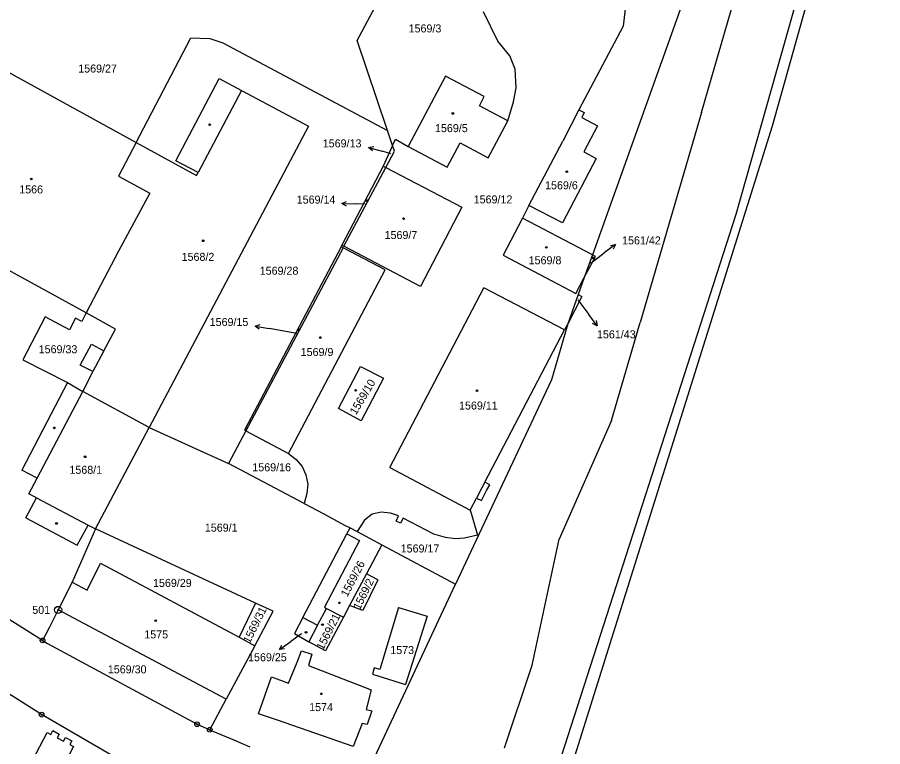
# Model space of a CAD drawing. Extents: x -763296 to -761805, y -1153670 to -1152034.
# Drawn here: x -762375.6 to -762191.7, y -1152457.5 to -1152302.6 of the extents above; entities that cross this region are included whole.
import ezdxf

# ---------------------------------------------------------------- set-up
doc = ezdxf.new("R2010")
doc.units = 0
for name, color, linetype in [('Vrstva 1', 7, 'Continuous'), ('Vrstva 13', 7, 'Continuous'), ('Vrstva 16', 7, 'Continuous'), ('Vrstva 17', 7, 'Continuous'), ('Vrstva 18', 7, 'Continuous'), ('Vrstva 19', 7, 'Continuous'), ('Vrstva 24', 7, 'Continuous'), ('Vrstva 25', 7, 'Continuous'), ('Vrstva 4', 7, 'Continuous')]:
    doc.layers.add(name, color=color, linetype=linetype)

msp = doc.modelspace()

# ---------------------------------------------------------------- linework, layer by layer
at = {"layer": 'Vrstva 1'}
for p, q in [((-762230.19, -1152322.79), (-762191.71, -1152189.12)), ((-762222.86, -1152344.39), (-762200.55, -1152265.44)), ((-762303.34, -1152307.53), (-762285.97, -1152274.85)), ((-762227.29, -1152280), (-762253.37, -1152353.02)), ((-762245.76, -1152295.43), (-762246.88, -1152304.45)), ((-762273.5, -1152307.66), (-762276.53, -1152301.44)), ((-762246.88, -1152304.45), (-762256.28, -1152322.2)), ((-762350.33, -1152329.15), (-762338.73, -1152306.91)), ((-762338.73, -1152306.91), (-762334.65, -1152307.08)), ((-762334.65, -1152307.08), (-762331.9, -1152307.96)), ((-762296.9, -1152326.63), (-762303.34, -1152307.53)), ((-762270.93, -1152310.77), (-762273.5, -1152307.66)), ((-762331.9, -1152307.96), (-762296.9, -1152326.63)), ((-762269.79, -1152313.56), (-762270.93, -1152310.77)), ((-762380.75, -1152312.44), (-762350.33, -1152329.15)), ((-762284.62, -1152315.07), (-762292.52, -1152330.03)), ((-762276.35, -1152319.42), (-762284.62, -1152315.07)), ((-762269.57, -1152317.55), (-762269.79, -1152313.56)), ((-762341.9, -1152333.04), (-762332.67, -1152315.59)), ((-762332.67, -1152315.59), (-762327.95, -1152318.09)), ((-762327.95, -1152318.09), (-762313.68, -1152325.69)), ((-762270.12, -1152320.5), (-762269.57, -1152317.55)), ((-762277.36, -1152321.36), (-762276.35, -1152319.42)), ((-762271.34, -1152324.54), (-762270.12, -1152320.5)), ((-762271.34, -1152324.54), (-762277.36, -1152321.36)), ((-762256.28, -1152322.2), (-762259.69, -1152328.87)), ((-762256.28, -1152322.2), (-762255.15, -1152322.77)), ((-762255.15, -1152322.77), (-762255.65, -1152323.83)), ((-762255.65, -1152323.83), (-762252.28, -1152325.64)), ((-762230.19, -1152322.79), (-762243.22, -1152367.38)), ((-762313.68, -1152325.69), (-762347.57, -1152389.71)), ((-762275.54, -1152332.41), (-762271.34, -1152324.54)), ((-762252.28, -1152325.64), (-762255.18, -1152331.17)), ((-762295.83, -1152329.8), (-762296.9, -1152326.63)), ((-762350.33, -1152329.15), (-762354.05, -1152336.29)), ((-762350.33, -1152329.15), (-762337.5, -1152336.19)), ((-762295.83, -1152329.8), (-762297.85, -1152334.16)), ((-762295.83, -1152329.8), (-762295.21, -1152328.47)), ((-762295.43, -1152330.99), (-762295.83, -1152329.8)), ((-762295.21, -1152328.47), (-762292.52, -1152330.03)), ((-762284.24, -1152334.41), (-762281.5, -1152329.22)), ((-762281.5, -1152329.22), (-762275.54, -1152332.41)), ((-762266.91, -1152342.54), (-762259.69, -1152328.87)), ((-762297.28, -1152334.47), (-762295.43, -1152330.99)), ((-762292.52, -1152330.03), (-762284.24, -1152334.41)), ((-762255.18, -1152331.17), (-762252.57, -1152332.54)), ((-762337.16, -1152335.54), (-762341.9, -1152333.04)), ((-762252.57, -1152332.54), (-762259.76, -1152346.25)), ((-762297.85, -1152334.16), (-762306.64, -1152350.96)), ((-762306.17, -1152351.2), (-762297.28, -1152334.47)), ((-762297.85, -1152334.16), (-762297.28, -1152334.47)), ((-762297.28, -1152334.47), (-762281.12, -1152342.92)), ((-762354.05, -1152336.29), (-762347.44, -1152339.96)), ((-762337.5, -1152336.19), (-762337.16, -1152335.54)), ((-762347.44, -1152339.96), (-762354.06, -1152352.23)), ((-762266.91, -1152342.54), (-762268.23, -1152345.21)), ((-762259.76, -1152346.25), (-762266.91, -1152342.54)), ((-762281.12, -1152342.92), (-762289.94, -1152359.73)), ((-762259.95, -1152459.53), (-762222.86, -1152344.39)), ((-762360.92, -1152365.36), (-762398.44, -1152344.76)), ((-762268.23, -1152345.21), (-762272.34, -1152353.13)), ((-762253.37, -1152353.02), (-762268.23, -1152345.21)), ((-762306.75, -1152351.29), (-762327.3, -1152390.26)), ((-762306.34, -1152351.51), (-762327.02, -1152390.41)), ((-762306.64, -1152350.96), (-762306.75, -1152351.29)), ((-762306.34, -1152351.51), (-762306.75, -1152351.29)), ((-762306.64, -1152350.96), (-762306.17, -1152351.2)), ((-762297.42, -1152356.21), (-762306.34, -1152351.51)), ((-762289.94, -1152359.73), (-762306.17, -1152351.2)), ((-762354.06, -1152352.23), (-762360.92, -1152365.36)), ((-762272.34, -1152353.13), (-762256.88, -1152361.23)), ((-762253.37, -1152353.02), (-762255.11, -1152357.86)), ((-762255.11, -1152357.86), (-762252.74, -1152353.36)), ((-762252.74, -1152353.36), (-762253.37, -1152353.02)), ((-762317.97, -1152395.21), (-762297.42, -1152356.21)), ((-762256.88, -1152361.23), (-762255.11, -1152357.86)), ((-762255.11, -1152357.86), (-762256.41, -1152361.48)), ((-762296.43, -1152398.22), (-762276.43, -1152360.01)), ((-762259.32, -1152368.96), (-762276.43, -1152360.01)), ((-762256.41, -1152361.48), (-762258.64, -1152367.67)), ((-762255.62, -1152361.89), (-762258.64, -1152367.67)), ((-762256.41, -1152361.48), (-762255.62, -1152361.89)), ((-762369.67, -1152366.21), (-762374.41, -1152375.3)), ((-762364.5, -1152368.95), (-762369.67, -1152366.21)), ((-762363.21, -1152366.51), (-762364.5, -1152368.95)), ((-762361.89, -1152367.21), (-762363.21, -1152366.51)), ((-762360.92, -1152365.36), (-762361.89, -1152367.21)), ((-762354.69, -1152368.78), (-762360.92, -1152365.36)), ((-762258.64, -1152367.67), (-762262.06, -1152379.6)), ((-762258.64, -1152367.67), (-762259.32, -1152368.96)), ((-762249.33, -1152388.23), (-762243.22, -1152367.38)), ((-762357.16, -1152373.45), (-762354.69, -1152368.78)), ((-762276.23, -1152401.31), (-762259.32, -1152368.96)), ((-762362.22, -1152376.45), (-762359.85, -1152372.03)), ((-762359.85, -1152372.03), (-762357.16, -1152373.45)), ((-762374.41, -1152375.3), (-762364.88, -1152380.16)), ((-762359.5, -1152377.84), (-762362.22, -1152376.45)), ((-762307.32, -1152385.68), (-762302.65, -1152376.73)), ((-762302.65, -1152376.73), (-762297.76, -1152379.23)), ((-762361.55, -1152381.86), (-762359.5, -1152377.84)), ((-762297.76, -1152379.23), (-762302.49, -1152388.27)), ((-762364.88, -1152380.16), (-762374.65, -1152398.73)), ((-762364.88, -1152380.16), (-762361.64, -1152382.03)), ((-762262.06, -1152379.6), (-762282.46, -1152422.96)), ((-762361.64, -1152382.03), (-762361.55, -1152381.86)), ((-762347.57, -1152389.71), (-762361.64, -1152382.03)), ((-762302.49, -1152388.27), (-762307.32, -1152385.68)), ((-762249.33, -1152388.23), (-762260.43, -1152413.42)), ((-762358.97, -1152411.25), (-762347.57, -1152389.71)), ((-762347.57, -1152389.71), (-762330.69, -1152397.32)), ((-762327.02, -1152390.41), (-762330.69, -1152397.32)), ((-762327.3, -1152390.26), (-762327.02, -1152390.41)), ((-762327.02, -1152390.41), (-762317.97, -1152395.21)), ((-762317.97, -1152395.21), (-762316.34, -1152396.49)), ((-762314.61, -1152405.86), (-762330.69, -1152397.32)), ((-762316.34, -1152396.49), (-762315.07, -1152397.96)), ((-762371.36, -1152400.45), (-762374.65, -1152398.73)), ((-762315.07, -1152397.96), (-762314.25, -1152399.74)), ((-762314.25, -1152399.74), (-762313.86, -1152401.71)), ((-762296.43, -1152398.22), (-762279.34, -1152407.25)), ((-762373.12, -1152403.79), (-762371.36, -1152400.45)), ((-762275.21, -1152401.85), (-762276.23, -1152401.31)), ((-762313.86, -1152401.71), (-762314.08, -1152403.72)), ((-762276.98, -1152405.22), (-762275.86, -1152403.09)), ((-762275.86, -1152403.09), (-762275.21, -1152401.85)), ((-762373.79, -1152408.9), (-762371.52, -1152404.64)), ((-762371.52, -1152404.64), (-762373.12, -1152403.79)), ((-762314.08, -1152403.72), (-762314.61, -1152405.86)), ((-762279.34, -1152407.25), (-762278, -1152404.68)), ((-762278, -1152404.68), (-762276.98, -1152405.22)), ((-762314.61, -1152405.86), (-762310.46, -1152408.07)), ((-762373.79, -1152408.9), (-762362.84, -1152414.72)), ((-762310.46, -1152408.07), (-762306.05, -1152410.42)), ((-762300.18, -1152408.14), (-762301.78, -1152409.4)), ((-762298.25, -1152407.69), (-762300.18, -1152408.14)), ((-762296.31, -1152407.87), (-762298.25, -1152407.69)), ((-762294.57, -1152408.49), (-762296.31, -1152407.87)), ((-762295.08, -1152409.59), (-762294.57, -1152408.49)), ((-762293.61, -1152408.94), (-762294.18, -1152410.01)), ((-762287.08, -1152412.35), (-762293.61, -1152408.94)), ((-762279.34, -1152407.25), (-762279.13, -1152407.92)), ((-762279.13, -1152407.92), (-762277.78, -1152412.6)), ((-762362.84, -1152414.72), (-762360.54, -1152410.45)), ((-762360.54, -1152410.45), (-762358.97, -1152411.25)), ((-762306.05, -1152410.42), (-762304.88, -1152411.04)), ((-762301.78, -1152409.4), (-762303.39, -1152411.82)), ((-762294.18, -1152410.01), (-762295.08, -1152409.59)), ((-762358.97, -1152411.25), (-762363.9, -1152422.54)), ((-762325, -1152427), (-762358.97, -1152411.25)), ((-762314.94, -1152430.08), (-762305.54, -1152412.31)), ((-762305.54, -1152412.31), (-762304.88, -1152411.04)), ((-762305.54, -1152412.31), (-762302.86, -1152413.71)), ((-762304.88, -1152411.04), (-762303.39, -1152411.82)), ((-762303.39, -1152411.82), (-762298.1, -1152414.65)), ((-762284.6, -1152413.05), (-762287.08, -1152412.35)), ((-762277.78, -1152412.6), (-762280.54, -1152413.23)), ((-762302.86, -1152413.71), (-762310.33, -1152427.9)), ((-762282.58, -1152413.35), (-762284.6, -1152413.05)), ((-762280.54, -1152413.23), (-762282.58, -1152413.35)), ((-762266.21, -1152440.18), (-762260.43, -1152413.42)), ((-762298.1, -1152414.65), (-762301.38, -1152420.8)), ((-762298.1, -1152414.65), (-762282.46, -1152422.96)), ((-762360.71, -1152424.22), (-762357.88, -1152418.55)), ((-762357.88, -1152418.55), (-762328.45, -1152434.26)), ((-762301.38, -1152420.8), (-762304.97, -1152427.52)), ((-762298.96, -1152422.05), (-762301.38, -1152420.8)), ((-762363.9, -1152422.54), (-762366.9, -1152428.44)), ((-762363.9, -1152422.54), (-762360.71, -1152424.22)), ((-762302.43, -1152465.69), (-762282.46, -1152422.96)), ((-762298.96, -1152422.05), (-762302.19, -1152428.57)), ((-762370.2, -1152434.94), (-762387.9, -1152423.92)), ((-762325, -1152427), (-762328.45, -1152434.26)), ((-762321.22, -1152428.75), (-762325, -1152427)), ((-762366.9, -1152428.44), (-762368.84, -1152432.27)), ((-762331.22, -1152447.4), (-762366.9, -1152428.44)), ((-762325.14, -1152436.06), (-762321.22, -1152428.75)), ((-762310.33, -1152427.9), (-762309.88, -1152428.13)), ((-762309.88, -1152428.13), (-762306.29, -1152430)), ((-762304.97, -1152427.52), (-762306.29, -1152430)), ((-762302.19, -1152428.57), (-762304.97, -1152427.52)), ((-762294.62, -1152427.97), (-762298.57, -1152441.12)), ((-762294.62, -1152427.97), (-762288.51, -1152429.8)), ((-762314.94, -1152430.08), (-762316.71, -1152433.47)), ((-762314.94, -1152430.08), (-762311.78, -1152431.71)), ((-762306.29, -1152430), (-762310.07, -1152437.11)), ((-762288.51, -1152429.8), (-762293.11, -1152444.3)), ((-762368.84, -1152432.27), (-762370.2, -1152434.94)), ((-762311.78, -1152431.71), (-762313.65, -1152435.23)), ((-762328.45, -1152434.26), (-762325.14, -1152436.06)), ((-762316.71, -1152433.47), (-762313.65, -1152435.23)), ((-762370.42, -1152450.7), (-762393.06, -1152436.49)), ((-762370.2, -1152434.94), (-762369.18, -1152435.6)), ((-762369.18, -1152435.6), (-762337.38, -1152452.75)), ((-762325.14, -1152436.06), (-762331.22, -1152447.4)), ((-762310.07, -1152437.11), (-762313.65, -1152435.23)), ((-762316.13, -1152439.57), (-762315.23, -1152437.12)), ((-762315.23, -1152437.12), (-762313.03, -1152437.87)), ((-762313.03, -1152437.87), (-762313.73, -1152440.27)), ((-762317.95, -1152443.98), (-762316.13, -1152439.57)), ((-762272.05, -1152457.76), (-762266.21, -1152440.18)), ((-762313.73, -1152440.27), (-762300.4, -1152445.4)), ((-762299.74, -1152440.77), (-762300.14, -1152442.07)), ((-762298.57, -1152441.12), (-762299.74, -1152440.77)), ((-762324.31, -1152450.52), (-762321.59, -1152442.68)), ((-762321.59, -1152442.68), (-762317.95, -1152443.98)), ((-762300.14, -1152442.07), (-762298.96, -1152442.44)), ((-762298.96, -1152442.44), (-762293.11, -1152444.3)), ((-762300.4, -1152445.4), (-762301.45, -1152449.57)), ((-762334.7, -1152453.89), (-762331.22, -1152447.4)), ((-762341.83, -1152467.23), (-762370.42, -1152450.7)), ((-762320.32, -1152451.9), (-762324.31, -1152450.52)), ((-762301.45, -1152449.57), (-762300.25, -1152449.87)), ((-762300.25, -1152449.87), (-762301.27, -1152452.79)), ((-762337.38, -1152452.75), (-762334.7, -1152453.89)), ((-762304.23, -1152457.49), (-762320.32, -1152451.9)), ((-762302.28, -1152452.55), (-762304.23, -1152457.49)), ((-762301.27, -1152452.79), (-762302.28, -1152452.55)), ((-762373.67, -1152462.84), (-762369.24, -1152454.47)), ((-762369.24, -1152454.47), (-762368.45, -1152454.88)), ((-762368.45, -1152454.88), (-762368.02, -1152454.09)), ((-762368.02, -1152454.09), (-762366.69, -1152454.82)), ((-762366.69, -1152454.82), (-762367.11, -1152455.6)), ((-762334.7, -1152453.89), (-762334.01, -1152454.19)), ((-762334.01, -1152454.19), (-762329.43, -1152456.14)), ((-762367.11, -1152455.6), (-762365.74, -1152456.32)), ((-762365.74, -1152456.32), (-762365.33, -1152455.53)), ((-762365.33, -1152455.53), (-762363.99, -1152456.26)), ((-762363.99, -1152456.26), (-762364.4, -1152457.03)), ((-762329.43, -1152456.14), (-762326.14, -1152457.54)), ((-762363.62, -1152457.44), (-762368.12, -1152465.82)), ((-762364.4, -1152457.03), (-762363.62, -1152457.44))]:
    msp.add_line(p, q, dxfattribs=at)
at = {"layer": 'Vrstva 13'}
for p, q in [((-762215.11, -1152325.64), (-762192.1, -1152243.03)), ((-762262.04, -1152475.19), (-762215.11, -1152325.64))]:
    msp.add_line(p, q, dxfattribs=at)
at = {"layer": 'Vrstva 16'}
for p, q in [((-762300.943, -1152330.202), (-762298.06, -1152331.03)), ((-762296.2, -1152331.56), (-762298.06, -1152331.03)), ((-762306.649, -1152342.143), (-762303.65, -1152342.22)), ((-762301.67, -1152342.27), (-762303.65, -1152342.22)), ((-762248.469, -1152350.808), (-762250.86, -1152352.62)), ((-762253.73, -1152354.8), (-762250.86, -1152352.62)), ((-762256.5, -1152362.57), (-762254.18, -1152365.7)), ((-762252.392, -1152368.109), (-762254.18, -1152365.7)), ((-762325.053, -1152368.142), (-762322.1, -1152368.67)), ((-762316.17, -1152369.73), (-762322.1, -1152368.67)), ((-762315.19, -1152433.56), (-762317.44, -1152435.16)), ((-762319.888, -1152436.894), (-762317.44, -1152435.16))]:
    msp.add_line(p, q, dxfattribs=at)
for points in [[(-762300.12, -1152330.958), (-762300.943, -1152330.202), (-762299.844, -1152329.997)], [(-762305.662, -1152342.668), (-762306.649, -1152342.143), (-762305.636, -1152341.669)], [(-762249.568, -1152351.013), (-762248.469, -1152350.808), (-762248.964, -1152351.81)], [(-762324.157, -1152368.81), (-762325.053, -1152368.142), (-762323.981, -1152367.826)], [(-762252.587, -1152367.008), (-762252.392, -1152368.109), (-762253.39, -1152367.604)], [(-762318.783, -1152436.724), (-762319.888, -1152436.894), (-762319.361, -1152435.908)]]:
    msp.add_lwpolyline(points, dxfattribs=at)
at = {"layer": 'Vrstva 24'}
for centre, radius in [((-762366.9, -1152428.44), 0.75), ((-762366.9, -1152428.44), 0.1), ((-762370.2, -1152434.94), 0.5), ((-762370.2, -1152434.94), 0.1), ((-762370.42, -1152450.7), 0.5), ((-762370.42, -1152450.7), 0.1), ((-762337.38, -1152452.75), 0.5), ((-762337.38, -1152452.75), 0.1), ((-762334.7, -1152453.89), 0.5), ((-762334.7, -1152453.89), 0.1)]:
    msp.add_circle(centre, radius, dxfattribs=at)
at = {"layer": 'Vrstva 25'}
for points in [[(-762307.04, -1152426.79), (-762306.95, -1152426.94), (-762307.04, -1152427.09), (-762307.22, -1152427.09), (-762307.31, -1152426.94), (-762307.22, -1152426.79)], [(-762314.16, -1152433.07), (-762314.07, -1152433.22), (-762314.16, -1152433.37), (-762314.34, -1152433.37), (-762314.43, -1152433.22), (-762314.34, -1152433.07)], [(-762310.91, -1152446.12), (-762310.82, -1152446.27), (-762310.91, -1152446.42), (-762311.09, -1152446.42), (-762311.18, -1152446.27), (-762311.09, -1152446.12)]]:
    msp.add_lwpolyline(points, close=True, dxfattribs=at)
for centre in [(-762283.05, -1152323), (-762334.71, -1152325.39), (-762258.83, -1152335.35), (-762372.6, -1152336.91), (-762301.32, -1152341.49), (-762293.49, -1152345.34), (-762336.08, -1152350.04), (-762263.18, -1152351.44), (-762253.26, -1152353.67), (-762315.8, -1152368.9), (-762311.21, -1152370.59), (-762303.69, -1152381.8), (-762277.9, -1152381.91), (-762367.71, -1152389.79), (-762361.17, -1152395.92), (-762367.25, -1152410.09), (-762346.17, -1152430.75), (-762310.74, -1152431.59)]:
    msp.add_circle(centre, 0.175, dxfattribs=at)
at = {"layer": 'Vrstva 4'}
for p, q in [((-762327.95, -1152318.09), (-762337.16, -1152335.54)), ((-762357.16, -1152373.45), (-762359.5, -1152377.84)), ((-762371.36, -1152400.45), (-762361.64, -1152382.03)), ((-762276.23, -1152401.31), (-762276.88, -1152402.55)), ((-762276.88, -1152402.55), (-762278, -1152404.68)), ((-762371.52, -1152404.64), (-762360.54, -1152410.45)), ((-762311.78, -1152431.71), (-762309.88, -1152428.13))]:
    msp.add_line(p, q, dxfattribs=at)

# ---------------------------------------------------------------- texts
at = {"layer": 'Vrstva 16'}
for s, p in [('1569/13', (-762310.677, -1152330.2)), ('1569/14', (-762316.213, -1152342.14)), ('1561/42', (-762247.077, -1152350.81)), ('1569/15', (-762334.707, -1152368.14)), ('1561/43', (-762252.417, -1152370.76)), ('1569/25', (-762326.55, -1152439.35))]:
    msp.add_text(s, height=1.7, dxfattribs=at).set_placement(p)
at = {"layer": 'Vrstva 17'}
msp.add_text('501', height=1.7, dxfattribs=at).set_placement((-762372.399, -1152429.29))
at = {"layer": 'Vrstva 18'}
for s, height, p in [('1569/3', 1.7, (-762292.438, -1152305.78)), ('1569/27', 1.7, (-762362.634, -1152314.3)), ('1569/13', 0.1, (-762296.45, -1152331.56)), ('1569/12', 1.7, (-762278.616, -1152342.1)), ('1569/28', 1.7, (-762324.074, -1152357.25)), ('1561/43', 0.1, (-762256.54, -1152362.35)), ('1569/33', 1.7, (-762371.035, -1152373.93)), ('1569/16', 1.7, (-762325.643, -1152399)), ('1569/1', 1.7, (-762335.733, -1152411.82)), ('1569/17', 1.7, (-762294.122, -1152416.25)), ('1569/29', 1.7, (-762346.744, -1152423.57)), ('1573', 1.7, (-762296.339, -1152437.83)), ('1569/30', 1.7, (-762356.344, -1152441.92))]:
    msp.add_text(s, height=height, dxfattribs=at).set_placement(p)
for s, rotation, p in [('1569/2', 63.65561, (-762302.818, -1152428.56)), ('1569/31', 63.59831, (-762326.2, -1152435.696))]:
    msp.add_text(s, height=1.7, rotation=rotation, dxfattribs=at).set_placement(p)
at = {"layer": 'Vrstva 19'}
for s, height, p in [('1569/5', 1.7, (-762286.828, -1152326.96)), ('1566', 1.7, (-762375.172, -1152339.98)), ('1569/6', 1.7, (-762263.441, -1152339.1)), ('1569/14', 0.1, (-762301.915, -1152342.27)), ('1569/7', 1.7, (-762297.541, -1152349.66)), ('1568/2', 1.7, (-762340.672, -1152354.3)), ('1569/8', 1.7, (-762266.931, -1152355.03)), ('1569/9', 1.7, (-762315.371, -1152374.51)), ('1569/11', 1.7, (-762281.725, -1152385.89)), ('1568/1', 1.7, (-762364.51, -1152399.54)), ('1575', 1.7, (-762348.599, -1152434.5)), ('1569/25', 0.1, (-762315.462, -1152433.56)), ('1574', 1.7, (-762313.572, -1152449.95))]:
    msp.add_text(s, height=height, dxfattribs=at).set_placement(p)
for s, height, rotation, p in [('1561/42', 0.1, 64.22857, (-762253.838, -1152355.024)), ('1569/15', 0.1, 62.10862, (-762316.286, -1152369.949)), ('1569/10', 1.7, 58.95736, (-762303.62, -1152387.149)), ('1569/26', 1.7, 62.22322, (-762305.466, -1152425.836)), ('1569/21', 1.7, 63.19724, (-762310.6, -1152437.111))]:
    msp.add_text(s, height=height, rotation=rotation, dxfattribs=at).set_placement(p)

doc.saveas('drawing.dxf')
